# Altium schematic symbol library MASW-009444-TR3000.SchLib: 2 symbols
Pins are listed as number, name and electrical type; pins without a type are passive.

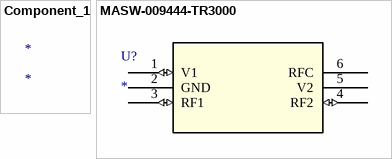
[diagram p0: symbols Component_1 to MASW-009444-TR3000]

## Component_1
designator *

## MASW-009444-TR3000
designator U?
No Description Available; Mfr_Name: MACOM
footprint PDFN6_1X1_MCM
pins: 1 V1 (io), 2 GND (power), 3 RF1 (io), 4 RF2 (io), 5 V2, 6 RFC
